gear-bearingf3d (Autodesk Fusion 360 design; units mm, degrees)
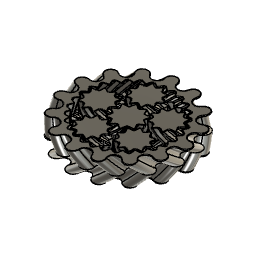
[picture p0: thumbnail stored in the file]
sketch "Sketch1" plane through (0, 0, 0) normal (0, 0, 1) x axis (1, 0, 0)
  line L1 (0, 0) -> (-20, 0)
  circle C1 centre (0, 0) radius 30
  circle C2 centre (0, 0) radius 10
  circle C3 centre (-20, 0) radius 10
  circle C4 centre (-6.1803, -19.0211) radius 10
  circle C5 centre (16.1803, -11.7557) radius 10
  circle C6 centre (16.1803, 11.7557) radius 10
  circle C7 centre (-6.1803, 19.0211) radius 10
  point P1 (0, 0)
  point P2 (0, 0)
  point P4 (-20, 0)
  point P5 (-20, 0)
  point P6 (0, 0)
  coincident P1 P2
  concentric C1 C2
  tangent C1 C3
  coincident P4 P5
  coincident P1 P6
  horizontal L1
  dimension "d1" diameter C1 = 60
  dimension "d2" diameter C2 = 20
  dimension "d3" diameter C3 = 20
  dimension "d5" C-Pattern1-Angle = 360
sketch "Sketch2" plane through (0, 0, 0) normal (0, 0, 1) x axis (1, 0, 0)
  line L1 (7.2342, 4.761) -> (6.3071, 4.1485)
  curve K1 (8.559, 8.4109) -> (7.2342, 4.761)
  curve K2 (7.2426, 4.7666) -> (7.2342, 4.761)
  curve K3 (7.2593, 4.7781) -> (7.2426, 4.7666)
  curve K4 (7.2836, 4.7964) -> (7.2593, 4.7781)
  curve K5 (7.3146, 4.8226) -> (7.2836, 4.7964)
  curve K6 (7.3513, 4.8579) -> (7.3146, 4.8226)
  curve K7 (7.3867, 4.8949) -> (7.3513, 4.8579)
  curve K8 (7.4211, 4.9331) -> (7.3867, 4.8949)
  curve K9 (7.4552, 4.9719) -> (7.4211, 4.9331)
  curve K10 (7.4889, 5.0111) -> (7.4552, 4.9719)
  curve K11 (7.5222, 5.0508) -> (7.4889, 5.0111)
  curve K12 (7.555, 5.0912) -> (7.5222, 5.0508)
  curve K13 (7.5871, 5.1324) -> (7.555, 5.0912)
  curve K14 (7.6184, 5.1744) -> (7.5871, 5.1324)
  curve K15 (7.6489, 5.2173) -> (7.6184, 5.1744)
  curve K16 (7.6788, 5.261) -> (7.6489, 5.2173)
  curve K17 (7.708, 5.3054) -> (7.6788, 5.261)
  curve K18 (7.7367, 5.3504) -> (7.708, 5.3054)
  curve K19 (7.7649, 5.3958) -> (7.7367, 5.3504)
  curve K20 (7.7927, 5.4417) -> (7.7649, 5.3958)
  curve K21 (7.8199, 5.4881) -> (7.7927, 5.4417)
  curve K22 (7.8467, 5.535) -> (7.8199, 5.4881)
  curve K23 (7.8729, 5.5824) -> (7.8467, 5.535)
  curve K24 (7.8985, 5.6304) -> (7.8729, 5.5824)
  curve K25 (7.9236, 5.6789) -> (7.8985, 5.6304)
  curve K26 (7.9482, 5.7278) -> (7.9236, 5.6789)
  curve K27 (7.9723, 5.7773) -> (7.9482, 5.7278)
  curve K28 (7.9958, 5.8271) -> (7.9723, 5.7773)
  curve K29 (8.0189, 5.8774) -> (7.9958, 5.8271)
  curve K30 (8.0415, 5.9281) -> (8.0189, 5.8774)
  curve K31 (8.0636, 5.9793) -> (8.0415, 5.9281)
  curve K32 (8.0852, 6.0308) -> (8.0636, 5.9793)
  curve K33 (8.1064, 6.0827) -> (8.0852, 6.0308)
  curve K34 (8.127, 6.135) -> (8.1064, 6.0827)
  curve K35 (8.1471, 6.1877) -> (8.127, 6.135)
  curve K36 (8.1668, 6.2408) -> (8.1471, 6.1877)
  curve K37 (8.186, 6.2942) -> (8.1668, 6.2408)
  curve K38 (8.2046, 6.3481) -> (8.186, 6.2942)
  curve K39 (8.2229, 6.4022) -> (8.2046, 6.3481)
  curve K40 (8.2406, 6.4567) -> (8.2229, 6.4022)
  curve K41 (8.2578, 6.5116) -> (8.2406, 6.4567)
  curve K42 (8.2746, 6.5667) -> (8.2578, 6.5116)
  curve K43 (8.2909, 6.6222) -> (8.2746, 6.5667)
  curve K44 (8.3067, 6.678) -> (8.2909, 6.6222)
  curve K45 (8.322, 6.7342) -> (8.3067, 6.678)
  curve K46 (8.3369, 6.7906) -> (8.322, 6.7342)
  curve K47 (8.3513, 6.8473) -> (8.3369, 6.7906)
  curve K48 (8.3652, 6.9044) -> (8.3513, 6.8473)
  curve K49 (8.3786, 6.9617) -> (8.3652, 6.9044)
  curve K50 (8.3916, 7.0193) -> (8.3786, 6.9617)
  curve K51 (8.404, 7.0772) -> (8.3916, 7.0193)
  curve K52 (8.4161, 7.1353) -> (8.404, 7.0772)
  curve K53 (8.4276, 7.1937) -> (8.4161, 7.1353)
  curve K54 (8.4387, 7.2524) -> (8.4276, 7.1937)
  curve K55 (8.4492, 7.3114) -> (8.4387, 7.2524)
  curve K56 (8.4594, 7.3706) -> (8.4492, 7.3114)
  curve K57 (8.469, 7.43) -> (8.4594, 7.3706)
  curve K58 (8.4782, 7.4897) -> (8.469, 7.43)
  curve K59 (8.4869, 7.5496) -> (8.4782, 7.4897)
  curve K60 (8.4951, 7.6098) -> (8.4869, 7.5496)
  curve K61 (8.5028, 7.6702) -> (8.4951, 7.6098)
  curve K62 (8.5101, 7.7308) -> (8.5028, 7.6702)
  curve K63 (8.5169, 7.7916) -> (8.5101, 7.7308)
  curve K64 (8.5233, 7.8526) -> (8.5169, 7.7916)
  curve K65 (8.5291, 7.9139) -> (8.5233, 7.8526)
  curve K66 (8.5345, 7.9753) -> (8.5291, 7.9139)
  curve K67 (8.5395, 8.037) -> (8.5345, 7.9753)
  curve K68 (8.5439, 8.0988) -> (8.5395, 8.037)
  curve K69 (8.5479, 8.1609) -> (8.5439, 8.0988)
  curve K70 (8.5514, 8.2231) -> (8.5479, 8.1609)
  curve K71 (8.5544, 8.2855) -> (8.5514, 8.2231)
  curve K72 (8.5565, 8.3356) -> (8.5544, 8.2855)
  curve K73 (8.5578, 8.3732) -> (8.5565, 8.3356)
  curve K74 (8.5586, 8.3984) -> (8.5578, 8.3732)
  curve K75 (8.559, 8.4109) -> (8.5586, 8.3984)
  curve K76 (4.761, 7.2342) -> (8.4109, 8.559)
  curve K77 (8.3984, 8.5586) -> (8.4109, 8.559)
  curve K78 (8.3732, 8.5578) -> (8.3984, 8.5586)
  curve K79 (8.3356, 8.5565) -> (8.3732, 8.5578)
  curve K80 (8.2855, 8.5544) -> (8.3356, 8.5565)
  curve K81 (8.2231, 8.5514) -> (8.2855, 8.5544)
  curve K82 (8.1609, 8.5479) -> (8.2231, 8.5514)
  curve K83 (8.0988, 8.5439) -> (8.1609, 8.5479)
  curve K84 (8.037, 8.5395) -> (8.0988, 8.5439)
  curve K85 (7.9753, 8.5345) -> (8.037, 8.5395)
  curve K86 (7.9139, 8.5291) -> (7.9753, 8.5345)
  curve K87 (7.8526, 8.5233) -> (7.9139, 8.5291)
  curve K88 (7.7916, 8.5169) -> (7.8526, 8.5233)
  curve K89 (7.7308, 8.5101) -> (7.7916, 8.5169)
  curve K90 (7.6702, 8.5028) -> (7.7308, 8.5101)
  curve K91 (7.6098, 8.4951) -> (7.6702, 8.5028)
  curve K92 (7.5496, 8.4869) -> (7.6098, 8.4951)
  curve K93 (7.4897, 8.4782) -> (7.5496, 8.4869)
  curve K94 (7.43, 8.469) -> (7.4897, 8.4782)
  curve K95 (7.3706, 8.4594) -> (7.43, 8.469)
  curve K96 (7.3114, 8.4492) -> (7.3706, 8.4594)
  curve K97 (7.2524, 8.4387) -> (7.3114, 8.4492)
  curve K98 (7.1937, 8.4276) -> (7.2524, 8.4387)
  curve K99 (7.1353, 8.4161) -> (7.1937, 8.4276)
  curve K100 (7.0772, 8.404) -> (7.1353, 8.4161)
  curve K101 (7.0193, 8.3916) -> (7.0772, 8.404)
  curve K102 (6.9617, 8.3786) -> (7.0193, 8.3916)
  curve K103 (6.9044, 8.3652) -> (6.9617, 8.3786)
  curve K104 (6.8473, 8.3513) -> (6.9044, 8.3652)
  curve K105 (6.7906, 8.3369) -> (6.8473, 8.3513)
  curve K106 (6.7342, 8.322) -> (6.7906, 8.3369)
  curve K107 (6.678, 8.3067) -> (6.7342, 8.322)
  curve K108 (6.6222, 8.2909) -> (6.678, 8.3067)
  curve K109 (6.5667, 8.2746) -> (6.6222, 8.2909)
  curve K110 (6.5116, 8.2578) -> (6.5667, 8.2746)
  curve K111 (6.4567, 8.2406) -> (6.5116, 8.2578)
  curve K112 (6.4022, 8.2229) -> (6.4567, 8.2406)
  curve K113 (6.3481, 8.2046) -> (6.4022, 8.2229)
  curve K114 (6.2942, 8.186) -> (6.3481, 8.2046)
  curve K115 (6.2408, 8.1668) -> (6.2942, 8.186)
  curve K116 (6.1877, 8.1471) -> (6.2408, 8.1668)
  curve K117 (6.135, 8.127) -> (6.1877, 8.1471)
  curve K118 (6.0827, 8.1064) -> (6.135, 8.127)
  curve K119 (6.0308, 8.0852) -> (6.0827, 8.1064)
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  dimension "d48" = 0.3
sketch "Sketch3" plane through (0, 0, 0) normal (0, 0, 1) x axis (1, 0, 0)
  line L1 (-11.8831, -1.6695) -> (-11.9104, -1.4619)
  line L2 (-10.9053, -1.4353) -> (-11.8967, -1.5657)
  line L3 (-9.7633, -1.7895) -> (-9.8937, -0.798)
  line L4 (-10.9053, -1.4353) -> (-9.8285, -1.2938)
  line L5 (-28.696, 1.5039) -> (-27.811, 1.4575)
  line L6 (-27.7998, 1.6573) -> (-27.8208, 1.2577)
  line L7 (-13.6109, -6.3891) -> (-26.3888, 6.3888)
  line L8 (-10.4569, 0.2528) -> (-10.1293, -0.0588)
  line L9 (-19.9998, -0.0002) -> (-26.8512, -0.9451)
  line L10 (-36.9263, -2.3346) -> (-26.8512, -0.9451)
  line L11 (0, 0) -> (-39.9999, 6.3354)
  arc A1 centre (-1.2344, -9.7455) radius 12.7508 clockwise from (-10.9053, -1.4353) to (-8.3397, 0.8422)
  arc A2 centre (-3.8162, 9.163) radius 12.7506 clockwise from (-7.8348, -2.9379) to (-10.9053, -1.4353)
  arc A3 centre (-8.4734, 5.1696) radius 12.7508 clockwise from (-4.6114, -6.9823) to (-7.9789, -7.5716)
  arc A4 centre (4.7191, -8.7322) radius 12.751 clockwise from (-7.9789, -7.5716) to (-7.2141, -4.2393)
  arc A5 centre (-9.8937, -0.798) radius 12.7509 clockwise from (0.3733, -8.3592) to (-2.0045, -10.8153)
  arc A6 centre (8.9505, -4.2908) radius 12.7508 clockwise from (-2.0045, -10.8153) to (-3.3443, -7.6702)
  arc A7 centre (-7.535, -6.4611) radius 12.7508 clockwise from (5.2155, -6.5433) to (4.7354, -9.928)
  arc A8 centre (9.7632, 1.7897) radius 12.7508 clockwise from (4.7354, -9.928) to (1.8029, -8.1711)
  arc A9 centre (-2.2982, -9.6561) radius 12.7508 clockwise from (8.0655, -2.2281) to (9.6666, -5.2485)
  arc A10 centre (6.8466, 7.1865) radius 12.7508 clockwise from (9.6666, -5.2485) to (6.2614, -5.5508)
  arc A11 centre (3.8165, -9.1628) radius 12.7508 clockwise from (7.8348, 2.9383) to (10.9054, 1.4357)
  arc A12 centre (1.3149, 9.8384) radius 12.7508 clockwise from (10.9054, 1.4357) to (8.3283, -0.8104)
  arc A13 centre (8.4734, -5.1696) radius 12.7508 clockwise from (4.6114, 6.9823) to (7.9788, 7.5716)
  arc A14 centre (-4.7191, 8.7323) radius 12.7508 clockwise from (7.9788, 7.5716) to (7.214, 4.2396)
  arc A15 centre (9.8936, 0.7983) radius 12.751 clockwise from (-0.3737, 8.3593) to (2.0043, 10.8156)
  arc A16 centre (-8.9505, 4.2908) radius 12.7508 clockwise from (2.0043, 10.8156) to (3.3443, 7.6702)
  arc A17 centre (7.535, 6.4611) radius 12.7508 clockwise from (-5.2155, 6.5433) to (-4.7355, 9.9279)
  arc A18 centre (-9.7633, -1.7895) radius 12.7506 clockwise from (-4.7355, 9.9279) to (-1.8032, 8.1711)
  arc A19 centre (2.2983, 9.6563) radius 12.7504 clockwise from (-8.0827, 2.2532) to (-9.666, 5.2487)
  arc A20 centre (-6.8466, -7.1865) radius 12.7508 clockwise from (-9.666, 5.2487) to (-6.2614, 5.5508)
  arc A21 centre (-8.8969, 1.6726) radius 1 clockwise from (-8.0827, 2.2532) to (-8.3397, 0.8422)
  arc A22 centre (-6.2155, 6.5498) radius 1 clockwise from (-5.2155, 6.5433) to (-6.2614, 5.5508)
  arc A23 centre (-1.1789, 8.9523) radius 1 clockwise from (-0.3737, 8.3593) to (-1.8032, 8.1711)
  arc A24 centre (4.3085, 7.9353) radius 1 clockwise from (4.6114, 6.9823) to (3.3443, 7.6702)
  arc A25 centre (8.1499, 3.8873) radius 1 clockwise from (7.8348, 2.9383) to (7.214, 4.2396)
  arc A26 centre (8.8783, -1.6455) radius 1 clockwise from (8.0655, -2.2281) to (8.3283, -0.8104)
  arc A27 centre (6.2155, -6.5498) radius 1 clockwise from (5.2155, -6.5433) to (6.2614, -5.5508)
  arc A28 centre (1.1786, -8.9522) radius 1 clockwise from (0.3733, -8.3592) to (1.8029, -8.1711)
  arc A29 centre (-4.3085, -7.9353) radius 1 clockwise from (-4.6114, -6.9823) to (-3.3443, -7.6702)
  arc A30 centre (-8.1499, -3.8869) radius 1 clockwise from (-7.8348, -2.9379) to (-7.2141, -4.2393)
  arc A31 centre (-28.9632, 1.4363) radius 1 clockwise from (-28.1646, 2.0381) to (-28.3844, 0.6208)
  arc A32 centre (-20.9816, -9.809) radius 12.7899 clockwise from (-30.8921, -1.7242) to (-28.3844, 0.6208)
  arc A33 centre (-24.0607, 9.0887) radius 12.7901 clockwise from (-27.7723, -3.151) to (-30.8921, -1.7242)
  arc A34 centre (-28.0625, -4.108) radius 1 clockwise from (-27.7723, -3.151) to (-27.1177, -4.4358)
  arc A35 centre (-15.002, -8.64) radius 12.8244 clockwise from (-27.8002, -7.821) to (-27.1177, -4.4358)
  arc A36 centre (-28.6491, 4.9831) radius 12.8322 clockwise from (-24.4386, -7.1387) to (-27.8002, -7.821)
  arc A37 centre (-24.1105, -8.0833) radius 1 clockwise from (-24.4386, -7.1387) to (-23.1536, -7.7929)
  arc A38 centre (-10.8855, -4.0699) radius 12.8206 clockwise from (-21.7215, -10.9219) to (-23.1536, -7.7929)
  arc A39 centre (-29.9241, -1.0673) radius 12.8216 clockwise from (-19.3984, -8.3889) to (-21.7215, -10.9219)
  arc A40 centre (-18.5775, -8.9599) radius 1 clockwise from (-19.3984, -8.3889) to (-17.9741, -8.1624)
  arc A41 centre (-10.2347, 2.0676) radius 12.8277 clockwise from (-15.0082, -9.8389) to (-17.9741, -8.1624)
  arc A42 centre (-27.4186, -6.6624) radius 12.8105 clockwise from (-14.6107, -6.4089) to (-15.0082, -9.8389)
  arc A43 centre (-13.6109, -6.3891) radius 1 clockwise from (-14.6107, -6.4089) to (-13.5916, -5.3893)
  arc A44 centre (-13.3451, 7.4288) radius 12.8205 clockwise from (-10.1574, -4.989) to (-13.5916, -5.3893)
  arc A45 centre (-22.0508, -9.7904) radius 12.826 clockwise from (-11.8341, -2.0363) to (-10.1574, -4.989)
  arc A46 centre (-11.0375, -1.4318) radius 1 clockwise from (-11.8341, -2.0363) to (-11.6089, -0.6111)
  arc A47 centre (-18.9442, 9.9242) radius 12.8374 clockwise from (-9.0677, 1.7233) to (-11.6089, -0.6111)
  arc A48 centre (-15.9348, -9.1198) radius 12.8347 clockwise from (-12.2103, 3.1627) to (-9.0677, 1.7233)
  arc A49 centre (-11.9201, 4.1196) radius 1 clockwise from (-12.2103, 3.1627) to (-12.8645, 4.4483)
  arc A50 centre (-24.9749, 8.6626) radius 12.8227 clockwise from (-12.18, 7.8182) to (-12.8645, 4.4483)
  arc A51 centre (-11.352, -4.99) radius 12.835 clockwise from (-15.5526, 7.1381) to (-12.18, 7.8182)
  arc A52 centre (-15.8799, 8.0831) radius 1 clockwise from (-15.5526, 7.1381) to (-16.837, 7.7935)
  arc A53 centre (-29.1093, 4.0809) radius 12.8215 clockwise from (-18.2643, 10.9204) to (-16.837, 7.7935)
  arc A54 centre (-10.0766, 1.0543) radius 12.821 clockwise from (-20.5927, 8.3884) to (-18.2643, 10.9204)
  arc A55 centre (-21.4129, 8.9604) radius 1 clockwise from (-20.5927, 8.3884) to (-22.017, 8.1635)
  arc A56 centre (-29.7652, -2.0589) radius 12.8271 clockwise from (-24.9897, 9.846) to (-22.017, 8.1635)
  arc A57 centre (-12.5785, 6.6627) radius 12.8129 clockwise from (-25.389, 6.4086) to (-24.9897, 9.846)
  arc A58 centre (-26.3888, 6.3888) radius 1 clockwise from (-25.389, 6.4086) to (-26.4088, 5.389)
  arc A59 centre (-26.6664, -7.4409) radius 12.8324 clockwise from (-29.8313, 4.9952) to (-26.4088, 5.389)
  arc A60 centre (-17.9128, 9.7647) radius 12.8374 clockwise from (-28.1646, 2.0381) to (-29.8313, 4.9952)
  arc A61 centre (-65.2554, 38.664) radius 52.1293 clockwise from (-28.696, 1.5039) to (-32.2557, -1.6905)
  arc A62 centre (-133.658, -90.1013) radius 139.3145 clockwise from (-31.9023, 5.0528) to (-28.696, 1.5039)
  arc A63 centre (-112.0041, -115.9215) radius 139.3145 clockwise from (-32.2557, -1.6905) to (-28.3816, -4.4952)
  arc A64 centre (-71.8681, 24.2518) radius 52.1293 clockwise from (-28.3816, -4.4952) to (-31.1994, -8.3599)
  arc A65 centre (-85.4551, -136.6753) radius 139.3145 clockwise from (-31.1994, -8.3599) to (-26.8268, -10.2979)
  arc A66 centre (-75.3398, 8.7796) radius 52.1293 clockwise from (-26.8268, -10.2979) to (-28.7795, -14.6639)
  arc A67 centre (-55.1713, -151.4557) radius 139.3145 clockwise from (-28.7795, -14.6639) to (-24.0996, -15.6504)
  arc A68 centre (-75.5189, -7.0763) radius 52.1293 clockwise from (-24.0996, -15.6504) to (-25.1018, -20.327)
  arc A69 centre (-22.4763, -159.6168) radius 139.3145 clockwise from (-25.1018, -20.327) to (-20.319, -20.319)
  arc A70 centre (-72.3974, -22.6229) radius 52.1293 clockwise from (-20.319, -20.319) to (-20.327, -25.1018)
  arc A71 centre (11.2011, -160.8019) radius 139.3145 clockwise from (-20.327, -25.1018) to (-15.6504, -24.0996)
  arc A72 centre (-66.1117, -37.1808) radius 52.1293 clockwise from (-15.6504, -24.0996) to (-14.6639, -28.7795)
  arc A73 centre (44.3889, -154.9591) radius 139.3145 clockwise from (-14.6639, -28.7795) to (-10.2979, -26.8268)
  arc A74 centre (-56.9367, -50.1137) radius 52.1293 clockwise from (-10.2979, -26.8268) to (-8.3599, -31.1994)
  arc A75 centre (75.6367, -142.3439) radius 139.3145 clockwise from (-8.3599, -31.1994) to (-4.4952, -28.3816)
  arc A76 centre (-45.2733, -60.8564) radius 52.1293 clockwise from (-4.4952, -28.3816) to (-1.6905, -32.2557)
  arc A77 centre (103.5788, -123.5076) radius 139.3145 clockwise from (-1.6905, -32.2557) to (1.5039, -28.696)
  arc A78 centre (-31.6312, -68.9394) radius 52.1293 clockwise from (1.5039, -28.696) to (5.0528, -31.9023)
  arc A79 centre (126.994, -99.2735) radius 139.3145 clockwise from (5.0528, -31.9023) to (7.4373, -27.7563)
  arc A80 centre (-16.6067, -74.0094) radius 52.1293 clockwise from (7.4373, -27.7563) to (11.5753, -30.1546)
  arc A81 centre (144.859, -70.7005) radius 139.3145 clockwise from (11.5753, -30.1546) to (13.0456, -25.6034)
  arc A82 centre (-0.8564, -75.8448) radius 52.1293 clockwise from (13.0456, -25.6034) to (17.5918, -27.0891)
  arc A83 centre (156.393, -39.0377) radius 139.3145 clockwise from (17.5918, -27.0891) to (18.0838, -22.3316)
  arc A84 centre (14.9314, -74.3655) radius 52.1293 clockwise from (18.0838, -22.3316) to (22.8395, -22.8395)
  arc A85 centre (161.0918, -5.6687) radius 139.3145 clockwise from (22.8395, -22.8395) to (22.3316, -18.0838)
  arc A86 centre (30.0665, -69.636) radius 52.1293 clockwise from (22.3316, -18.0838) to (27.0891, -17.5918)
  arc A87 centre (158.7502, 27.9481) radius 139.3145 clockwise from (27.0891, -17.5918) to (25.6034, -13.0456)
  arc A88 centre (43.8877, -61.8631) radius 52.1293 clockwise from (25.6034, -13.0456) to (30.1546, -11.5753)
  arc A89 centre (149.4704, 60.3433) radius 139.3145 clockwise from (30.1546, -11.5753) to (27.7563, -7.4373)
  arc A90 centre (55.7907, -51.3865) radius 52.1293 clockwise from (27.7563, -7.4373) to (31.9023, -5.0528)
  arc A91 centre (133.658, 90.1013) radius 139.3145 clockwise from (31.9023, -5.0528) to (28.696, -1.5039)
  arc A92 centre (65.2554, -38.664) radius 52.1293 clockwise from (28.696, -1.5039) to (32.2557, 1.6905)
  arc A93 centre (112.0041, 115.9215) radius 139.3145 clockwise from (32.2557, 1.6905) to (28.3816, 4.4952)
  arc A94 centre (71.8681, -24.2518) radius 52.1293 clockwise from (28.3816, 4.4952) to (31.1994, 8.3599)
  arc A95 centre (85.4551, 136.6753) radius 139.3145 clockwise from (31.1994, 8.3599) to (26.8268, 10.2979)
  arc A96 centre (75.3398, -8.7796) radius 52.1293 clockwise from (26.8268, 10.2979) to (28.7795, 14.6639)
  arc A97 centre (55.1713, 151.4557) radius 139.3145 clockwise from (28.7795, 14.6639) to (24.0996, 15.6504)
  arc A98 centre (75.5189, 7.0763) radius 52.1293 clockwise from (24.0996, 15.6504) to (25.1018, 20.327)
  arc A99 centre (22.4763, 159.6168) radius 139.3145 clockwise from (25.1018, 20.327) to (20.319, 20.319)
  arc A100 centre (72.3974, 22.6229) radius 52.1293 clockwise from (20.319, 20.319) to (20.327, 25.1018)
  arc A101 centre (-11.2011, 160.8019) radius 139.3145 clockwise from (20.327, 25.1018) to (15.6504, 24.0996)
  arc A102 centre (66.1117, 37.1808) radius 52.1293 clockwise from (15.6504, 24.0996) to (14.6639, 28.7795)
  arc A103 centre (-44.3889, 154.9591) radius 139.3145 clockwise from (14.6639, 28.7795) to (10.2979, 26.8268)
  arc A104 centre (56.9367, 50.1137) radius 52.1293 clockwise from (10.2979, 26.8268) to (8.3599, 31.1994)
  arc A105 centre (-75.6367, 142.3439) radius 139.3145 clockwise from (8.3599, 31.1994) to (4.4952, 28.3816)
  arc A106 centre (45.2733, 60.8564) radius 52.1293 clockwise from (4.4952, 28.3816) to (1.6905, 32.2557)
  arc A107 centre (-103.5788, 123.5076) radius 139.3145 clockwise from (1.6905, 32.2557) to (-1.5039, 28.696)
  arc A108 centre (31.6312, 68.9394) radius 52.1293 clockwise from (-1.5039, 28.696) to (-5.0528, 31.9023)
  arc A109 centre (-126.994, 99.2735) radius 139.3145 clockwise from (-5.0528, 31.9023) to (-7.4373, 27.7563)
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  point P4 (-11.8967, -1.5657)
  point P11 (-9.8937, -0.798)
  point P35 (-9.8937, -0.798)
  point P31 (-9.7633, -1.7895)
  point P36 (-9.7633, -1.7895)
  point P37 (-9.8285, -1.2938)
  point P1 (0, 0)
  point P281 (0, 0)
  point P522 (0, 0)
  point P117 (-26.3888, 6.3888)
  point P523 (-26.3888, 6.3888)
  point P114 (-13.6109, -6.3891)
  point P524 (-13.6109, -6.3891)
  point P525 (-19.9998, -0.0002)
  point P529 (-19.9998, -0.0002)
  point P532 (-36.9263, -2.3346)
  point P533 (-36.9263, -2.3346)
  point P535 (0, 0)
  point P138 (-32.2557, -1.6905)
  point P280 (-31.9023, 5.0528)
  point P568 (0, 0)
  point P636 (0, 0)
  point P5 (-10.9053, -1.4353)
  midpoint L1 P4
  perpendicular L1 L2
  coincident P11 P35
  coincident P31 P36
  midpoint L3 P37
  parallel L2 L4
  perpendicular L3 L4
  tangent A19 A21
  tangent A1 A21
  tangent A20 A22
  tangent A17 A22
  tangent A18 A23
  tangent A15 A23
  equal A22 A23
  tangent A16 A24
  tangent A13 A24
  equal A22 A24
  tangent A14 A25
  tangent A11 A25
  equal A22 A25
  tangent A12 A26
  tangent A9 A26
  equal A22 A26
  tangent A7 A27
  tangent A10 A27
  equal A22 A27
  tangent A5 A28
  tangent A8 A28
  equal A22 A28
  tangent A3 A29
  tangent A6 A29
  equal A22 A29
  tangent A4 A30
  tangent A2 A30
  equal A22 A30
  tangent A31 A60
  tangent A31 A32
  tangent A58 A59
  tangent A57 A58
  tangent A55 A56
  tangent A54 A55
  equal A55 A58
  tangent A52 A53
  tangent A51 A52
  equal A52 A58
  tangent A49 A50
  tangent A48 A49
  equal A49 A58
  tangent A46 A47
  tangent A45 A46
  equal A46 A58
  tangent A42 A43
  tangent A43 A44
  equal A43 A58
  tangent A39 A40
  tangent A40 A41
  equal A40 A58
  tangent A36 A37
  tangent A37 A38
  equal A37 A58
  tangent A34 A35
  tangent A33 A34
  equal A34 A58
  perpendicular L5 L6
  coincident P1 P281
  coincident P1 P522
  coincident P117 P523
  coincident P114 P524
  midpoint L7 P525
  coincident P525 P529
  coincident P532 P533
  coincident P281 P535
  coincident P138 L9
  parallel L9 L10
  coincident P280 L11
  coincident P568 P636
  dimension "d53" distance P4 P5 = 1
  dimension "d56" distance P35 P36 = 1
  dimension "d57" radius A21 = 1 (= "d58")
  dimension "d58" radius A22 = 1
  dimension "d59" radius A31 = 1 (= "d58")
  dimension "d60" radius A58 = 1
  dimension "d63" = 0.03
  dimension "d65" = 0.3
  dimension "d170" diameter = 74
  dimension "d175" diameter = 12
  dimension "d181" radius = 3.5
  dimension "d203" diameter = 90
  dimension "d62" C-Pattern1-Angle = 360
  dimension "d183" C-Pattern2-Angle = 360
  dimension "d185" C-Pattern3-Angle = 360
sketch "Sketch4" plane through (0, 0, 0) normal (0, 1, 0) x axis (1, 0, 0)
  line L1 (0, -7) -> (0, 0)
  line L2 (-19.9998, -7) -> (-19.9998, 0)
  point P1 (0, 0)
  point P2 (0, 0)
  point P4 (-19.9998, 0)
  point P6 (-19.9998, 0)
  point P3 (0, -7)
  point P5 (-19.9998, -7)
  coincident P1 P2
  vertical L1
  vertical L2
  coincident P4 P6
  dimension "d66" distance P2 P3 = 7
  dimension "d67" distance P4 P5 = 7 (= "d66")
sweep "Sweep1" sketch "Sketch3" TwistAngle -41.5 TaperAngle 0
sweep "Sweep2" sketch "Sketch3" TwistAngle 43 TaperAngle 0
sweep "Sweep3" sketch "Sketch3" TwistAngle 14.4 TaperAngle 0
fillet "Fillet1" radius 0.5
circular_pattern "C-Pattern1" TotalAngle 360
mirror "Mirror1" mirrorStitchTolerance 0.1
sketch "Sketch5" plane through (0, 0, 14) normal (0, 0, 1) x axis (-1, 0, 0)
  line L1 (-5.7735, 0) -> (-2.8868, 5)
  line L2 (-2.8868, -5) -> (-5.7735, 0)
  line L3 (2.8868, -5) -> (-2.8868, -5)
  line L4 (5.7735, 0) -> (2.8868, -5)
  line L5 (2.8868, 5) -> (5.7735, 0)
  line L6 (-2.8868, 5) -> (2.8868, 5)
  curve K1 (-10.6707, -2.0605) -> (-10.8404, -0.7715)
  curve K2 (-7.4216, -7.9391) -> (-8.3166, -6.9959)
  curve K3 (-1.3376, -10.7854) -> (-2.616, -10.5485)
  curve K4 (5.2571, -9.5115) -> (4.0836, -10.0713)
  curve K5 (9.8435, -4.6052) -> (9.2231, -5.7478)
  curve K6 (10.6748, 2.0569) -> (10.8475, 0.7712)
  curve K7 (7.4212, 7.939) -> (8.3162, 6.9959)
  curve K8 (1.3378, 10.7851) -> (2.6162, 10.5481)
  curve K9 (-5.2571, 9.5117) -> (-4.0836, 10.0714)
  curve K10 (-9.8439, 4.6051) -> (-9.2235, 5.7477)
  arc A1 centre (-3.8165, 9.1628) radius 13.1508 clockwise from (-7.9608, -3.3179) to (-10.6707, -2.0605)
  arc A2 centre (-8.1499, -3.8873) radius 0.6 clockwise from (-7.9608, -3.3179) to (-7.5884, -4.0987)
  arc A3 centre (4.7191, -8.7323) radius 13.1508 clockwise from (-8.3166, -6.9959) to (-7.5884, -4.0987)
  arc A4 centre (-8.4734, 5.1696) radius 13.1508 clockwise from (-4.4902, -7.3635) to (-7.4216, -7.9391)
  arc A5 centre (-4.3085, -7.9353) radius 0.6 clockwise from (-4.4902, -7.3635) to (-3.73, -7.7763)
  arc A6 centre (8.9505, -4.2908) radius 13.1508 clockwise from (-2.616, -10.5485) to (-3.73, -7.7763)
  arc A7 centre (-9.8936, -0.7983) radius 13.151 clockwise from (0.6958, -8.5965) to (-1.3376, -10.7854)
  arc A8 centre (1.1789, -8.9523) radius 0.6 clockwise from (0.6958, -8.5965) to (1.5535, -8.4836)
  arc A9 centre (9.7633, 1.7895) radius 13.1505 clockwise from (4.0836, -10.0713) to (1.5535, -8.4836)
  arc A10 centre (-7.535, -6.4611) radius 13.1508 clockwise from (5.6155, -6.5459) to (5.2571, -9.5115)
  arc A11 centre (6.2155, -6.5498) radius 0.6 clockwise from (5.6155, -6.5459) to (6.243, -5.9504)
  arc A12 centre (6.8466, 7.1865) radius 13.1508 clockwise from (9.2231, -5.7478) to (6.243, -5.9504)
  arc A13 centre (-2.2983, -9.6563) radius 13.1505 clockwise from (8.4086, -2.0208) to (9.8435, -4.6052)
  arc A14 centre (8.8969, -1.6726) radius 0.5998 clockwise from (8.4086, -2.0208) to (8.5627, -1.1745)
  arc A15 centre (1.2344, 9.7455) radius 13.151 clockwise from (10.8475, 0.7712) to (8.5627, -1.1745)
  arc A16 centre (3.8162, -9.163) radius 13.1501 clockwise from (7.9607, 3.317) to (10.6748, 2.0569)
  arc A17 centre (8.1499, 3.8869) radius 0.6005 clockwise from (7.9607, 3.317) to (7.5879, 4.0985)
  arc A18 centre (-4.7191, 8.7322) radius 13.1505 clockwise from (8.3162, 6.9959) to (7.5879, 4.0985)
  arc A19 centre (8.4734, -5.1696) radius 13.1508 clockwise from (4.4902, 7.3635) to (7.4212, 7.939)
  arc A20 centre (4.3085, 7.9353) radius 0.6 clockwise from (4.4902, 7.3635) to (3.73, 7.7763)
  arc A21 centre (-8.9505, 4.2908) radius 13.1508 clockwise from (2.6162, 10.5481) to (3.73, 7.7763)
  arc A22 centre (9.8937, 0.798) radius 13.1509 clockwise from (-0.6954, 8.5964) to (1.3378, 10.7851)
  arc A23 centre (-1.1786, 8.9522) radius 0.6 clockwise from (-0.6954, 8.5964) to (-1.5531, 8.4835)
  arc A24 centre (-9.7632, -1.7897) radius 13.1508 clockwise from (-4.0836, 10.0714) to (-1.5531, 8.4835)
  arc A25 centre (7.535, 6.4611) radius 13.1508 clockwise from (-5.6155, 6.5459) to (-5.2571, 9.5117)
  arc A26 centre (-6.2155, 6.5498) radius 0.6 clockwise from (-5.6155, 6.5459) to (-6.243, 5.9504)
  arc A27 centre (-6.8466, -7.1865) radius 13.1508 clockwise from (-9.2235, 5.7477) to (-6.243, 5.9504)
  arc A28 centre (2.2982, 9.6561) radius 13.1508 clockwise from (-8.3906, 1.995) to (-9.8439, 4.6051)
  arc A29 centre (-8.8783, 1.6455) radius 0.6 clockwise from (-8.3906, 1.995) to (-8.5483, 1.1444)
  arc A30 centre (-1.3149, -9.8384) radius 13.1508 clockwise from (-10.8404, -0.7715) to (-8.5483, 1.1444)
  point P1 (0, 0)
  point P8 (0, 0)
  coincident P1 P8
extrude "Extrude1" cut sketch "Sketch5" profile of L1 L2 L3 L4 L5 L6 against normal blind 21
fillet "Fillet2" radius 0.3
copy_paste_bodies "CutPasteBodies1"
copy_paste_bodies "CutPasteBodies1"
copy_paste_bodies "CutPasteBodies1"
scale "Scale1" ScaleFactor 0.6
sketch "Sketch7" plane through (0, 0, 0) normal (0, 1, 0) x axis (1, 0, 0)
  line L1 (-35.6125, -8) -> (35.6125, -8)
  line L2 (-36.5, 0) -> (0, 0)
  line L3 (35.6125, 8) -> (-35.6125, 8)
  line L4 (0, -8) -> (0, 8)
  circle C1 centre (0, 0) radius 10
  circle C2 centre (0, 0) radius 10.3
  circle C3 centre (0, 0) radius 15.3
  circle C4 centre (0, 0) radius 15.6
  circle C5 centre (0, 0) radius 20.6
  circle C6 centre (0, 0) radius 20.9
  circle C7 centre (0, 0) radius 25.9
  circle C8 centre (0, 0) radius 26.2
  circle C9 centre (0, 0) radius 31.2
  circle C10 centre (0, 0) radius 31.5
  circle C11 centre (0, 0) radius 36.5
  point P1 (0, 0)
  point P2 (0, 0)
  point P3 (0, 0)
  point P11 (0, 0)
  point P15 (0, 0)
  point P17 (-35.6125, 8)
  point P18 (35.6125, 8)
  point P13 (35.6125, -8)
  point P14 (-35.6125, -8)
  point P16 (-36.5, 0)
  point P19 (0, 8)
  point P20 (0, -8)
  coincident P1 P2
  coincident P1 P3
  concentric C2 C3
  concentric C2 C4
  concentric C4 C5
  concentric C2 C6
  concentric C6 C7
  concentric C5 C8
  concentric C8 C9
  concentric C1 C10
  concentric C7 C11
  horizontal L1
  coincident P11 P15
  horizontal L2
  horizontal L3
  coincident C11 P17
  coincident C11 P18
  coincident C11 P13
  coincident C11 P14
  coincident C11 P16
  midpoint L3 P19
  midpoint L1 P20
  dimension "d187" diameter C1 = 20
  dimension "d188" distance C1 C2 = 0.3
  dimension "d189" distance C2 C3 = 5
  dimension "d190" distance C3 C4 = 0.3 (= "d188")
  dimension "d191" distance C4 C5 = 5 (= "d189")
  dimension "d192" distance C5 C6 = 0.3 (= "d188")
  dimension "d193" distance C6 C7 = 5 (= "d189")
  dimension "d194" distance C7 C8 = 0.3 (= "d188")
  dimension "d195" distance C8 C9 = 5 (= "d189")
  dimension "d196" distance C9 C10 = 0.3 (= "d188")
  dimension "d197" distance C10 C11 = 5 (= "d189")
  dimension "d198" distance L2 L3 = 8
  dimension "d199" distance L1 L2 = 8
revolve "Revolve1" sketch "Sketch7" AlongAngle 360
fillet "Fillet3" radius 0.5
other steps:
base_feature "Base Feature1"
base_feature "Base Feature1"
scale "Scale1" ScaleFactor 0.6
base_feature "Base Feature1"
scale "Scale1" ScaleFactor 0.6
create_component "CreateComponent8"
create_component "CreateComponent9"
remove_body "RemoveBody1"
remove_body "RemoveBody2"
remove_body "RemoveBody3"
remove_body "RemoveBody4"
remove_body "RemoveBody5"
remove_body "RemoveBody6"
create_component "CreateComponent10"
remove_body "RemoveBody7"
